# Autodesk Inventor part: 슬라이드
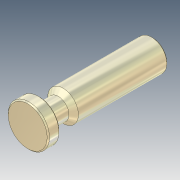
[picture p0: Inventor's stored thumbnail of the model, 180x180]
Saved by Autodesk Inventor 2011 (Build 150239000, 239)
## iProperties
Company: 한국ATC센터
Created: 2014-11
Part Number: 슬라이드
Document SubType Name: Modeling
Designer: KYOUNG IL JANG
Density: 7.86 g/cm^3
Material: 강, 연강
Mass: 436.103 g
Surface Area: 105.764 cm^2
Volume: 55.4838 cm^3
Author: KYOUNG IL JANG
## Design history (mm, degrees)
sketch "스케치1"
  geometry: L1 (19, 106.5)-(-19, 106.5) reference; L2 (0, 106.5)-(0, 212.5); L3 (0, 212.5)-(-13, 212.5); L4 (-13, 212.5)-(-13, 136.5); L5 (-9, 116.5)-(-17.5, 116.5); L6 (-17.5, 116.5)-(-17.5, 106.5); L7 (-17.5, 106.5)-(0, 106.5); L8 (-9, 116.5)-(-9, 132.5); L9 (-9, 132.5)-(-13, 136.5); 1 further point
  constraints: 18 end point, 3 perpendicular, 1 collinear, 1 horizontal, 1 midpoint, 1 parallel, 2 other
  dimensions: "d0" = 10 distance between parallel lines of L5 L7; "d1" = 35 diameter of L6 L2; "d2" = 106 distance of L2.start L2.end; "d3" = 135 deg angle of L9 L4; "d4" = 18 diameter of L8 L2; "d5" = 30 distance from line of L4.end L7; "d11" = 26 diameter of L4 L2
revolve "회전1" sketch "스케치1" stored, may be unused: angle "d6" = 90 deg
chamfer "모따기1" distance "d7" = 1; stored, may be unused: second distance "d8" = 2, angle "d9" = 45 deg
fillet "모깎기1" dims "d10" = 2
node "솔리드1"
